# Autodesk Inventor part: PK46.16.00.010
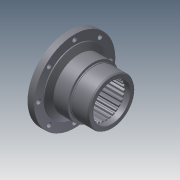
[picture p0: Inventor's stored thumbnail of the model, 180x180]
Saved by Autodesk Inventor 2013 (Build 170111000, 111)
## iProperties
Shininess: 25.0
Length Units: 11269
Angle Units: 11279
Time Units: 11290
Mass Units: 11283
Length Display Precision: 3
Angle Display Precision: 2
Created: 2001-08
Part Number: PK46.16.00.010
Material: Steel, Mild
Document SubType Name: Modeling
Designer: SOleg
Density: 7.86 g/cm^3
Mass: 4404.42 g
Surface Area: 1072.64 cm^2
Volume: 560.359 cm^3
Density: 0.0
Volumn: 0.0
Area: 0.0
PropertySet Name: Model Information
Control State: 0
Master: False
Checked Out: False
Checked Out Date: 2008-10-09
Last Check In Date: 2008-10-09
Author: SOleg
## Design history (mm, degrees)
sketch "Sketch1"
  geometry: L1 (45, 40)-(45, 48.268); L2 (33, 40)-(45, 40); L3 (33, 40.5)-(33, 40); L4 (-22, 40.5)-(33, 40.5); L5 (-22, 35)-(-22, 40.5); L6 (-26, 35)-(-22, 35); L7 (-26, 40)-(-26, 35); L8 (-33, 40)-(-26, 40); L9 (-33, 35)-(-33, 40); L10 (-40, 35)-(-33, 35); L11 (-40, 45)-(-40, 35); L12 (-45, 45)-(-40, 45); L13 (-45, 55)-(-45, 45); L14 (7, 55)-(-45, 55); L15 (7, 49)-(7, 55); L16 (12, 49)-(7, 49); L17 (12, 50)-(12, 49); L18 (42, 50)-(12, 50); L19 (45, 48.268)-(42, 50); L20 (-45, 0)-(45, 0); L21 (-45, 0)-(45, 0)
  constraints: 42 end point, 10 horizontal, 9 vertical, 2 collinear, 1 other
  dimensions: "d1" = 50 vertical distance of L18.start L20.end; "d3" = 40 distance of L1.start L20.end; "d5" = 40.5 vertical distance of L3.start L20.end; "d7" = 35 vertical distance of L5.start L20.start; "d9" = 45 vertical distance of L11.start L20.start; "d11" = 55 distance of L13.start L20.start; "d13" = 67 horizontal distance of L4.start L1.end; "d15" = 12 distance of L2.start L1.start; "d17" = 5 distance of L16.start L15.start; "d19" = 90 horizontal distance of L1.start L12.start; "d23" = 18 horizontal distance of L4.start L10.start; "d25" = 7 distance of L8.start L7.start; "d27" = 7 distance of L10.start L9.start; "d29" = 30 deg angle of L18 L19; "d31" = 3 horizontal distance of L1.end L18.start; "d33" = 49 vertical distance of L16.start L20.end; "d90" = 38 distance between parallel lines of L15 L1
revolve "RevolutionFull1" sketch "Sketch1" stored, may be unused: angle "d34" = 360 deg
workplane "Work Plane1"
node "WorkPlane1"
sketch "Sketch2"
  geometry: L1 (-41.54, -4.27)-(-37.25, -1.145); L2 (-41.54, 4.27)-(-41.54, -4.27); L3 (-37.25, 1.145)-(-41.54, 4.27); L4 (-37.25, -1.145)-(-37.25, 1.145); C1 r 55 at (0, 0) reference; C2 r 35 at (0, 0) reference
  constraints: 8 end point, 2 vertical
  dimensions: "d41" = 8.54 distance of L2.start L1.start; "d43" = 2.29 distance of L1.end L3.start; "d45" = 4.29 horizontal distance of L3.start L2.start; "d47" = 4.27 vertical distance of L1.start C1.centre; "d49" = 1.145 vertical distance of L1.end C2.centre; "d51" = 37.25 horizontal distance of L3.start C2.centre
extrude "ExtrusionBlind1" join sketch "Sketch2" distance "d52" = 55; taper "d53" = 0 deg
node "WorkPlane2"
node "WorkPlane3"
sketch "Sketch3"
  geometry: L1 (18.5, -87.5)-(18.5, -67.5); L2 (32.5, -87.5)-(18.5, -87.5); L3 (32.5, -67.5)-(32.5, -87.5); L4 (28.5, -67.5)-(32.5, -67.5); L5 (28.5, -55)-(28.5, -67.5); L6 (9.283, -55)-(28.5, -55); L7 (16.5, -67.5)-(9.283, -55); L8 (28.5, 45)-(28.5, -45) reference; L9 (23.5, 35)-(23.5, -35) reference; L10 (-184.647, 0)-(153.932, 0); L11 (-61.5, 48.268)-(-61.5, -48.268) reference; L12 (28.5, 55)-(28.5, -55) reference; L13 (28.5, -55)-(-23.5, -55) reference; L14 (28.5, 0)-(80.478, 0); L15 (28.5, -55)-(28.5, -55); L16 (16.5, -67.5)-(18.5, -67.5); L17 (16.5, -67.5)-(18.5, -67.5); L18 (9.283, -55)-(28.5, -55)
  constraints: 27 end point, 3 collinear, 3 horizontal, 3 parallel, 3 vertical, 1 midpoint, 1 perpendicular
  dimensions: "d66" = 14 distance of L2.start L1.start; "d91" = 175 diameter of L2 L10; "d92" = 135 diameter of L4 L10; "d93" = 94 distance between parallel lines of L3 L11; "d94" = 2 distance of L7.start L1.end; "d95" = 135 diameter of L16 L10; "d99" = 4 distance of L4.start L3.start; "d100" = 60 deg angle of L7 L13
revolve "RevolutionAngle1" sketch "Sketch3" stored, may be unused: angle "d69" = 360 deg
workaxis "Work Axis2"
sketch "Sketch7"
  geometry: C1 r 87.5 at (0, 0) reference; C2 r 5 at (0, 77.5)
  constraints: 1 centre point
  dimensions: "d101" = 10 diameter of C2; "d102" = 0 horizontal distance of C1.centre C2.centre; "d103" = 77.5 distance of C1.centre C2.centre
extrude "Extrusion3" cut sketch "Sketch7" stored distance "d104" = 10; taper "d105" = 0 deg
pattern_circular "Circular Pattern3" dims angle "d108" = 360 deg
sketch "Sketch8"
  geometry: L1 (-67.8, 0)-(63.8, 0) reference; L2 (7, 55)-(-45, 55) reference; L3 (7, 49)-(12, 49) reference; L4 (7, 55)-(5, 55); L5 (5, 55)-(5, 50); L6 (5, 50)-(7, 50); L7 (7, 50)-(7, 55); L8 (5, 68)-(5, -68) reference; L9 (12, 50)-(42, 50) reference; 1 further point
  constraints: 10 end point, 2 collinear, 2 parallel, 1 horizontal, 1 perpendicular, 1 vertical, 2 other
revolve "Revolution4" sketch "Sketch8" stored, may be unused: angle "d109" = 90 deg
body "Solid1"
pattern_circular "PolarArray1" dims angle "d56" = 360 deg
other parameters: "d4" = 40.5 (derived), "d6" = 35 (derived), "d8" = 45 (derived), "d10" = 55 (derived), "d12" = 67 (derived), "d14" = 12 (derived), "d16" = 5 (derived), "d20" = 28 (derived), "d22" = 18 (derived), "d24" = 7 (derived), "d26" = 7 (derived), "d28" = 30 deg (derived), "d30" = 3 (derived), "d32" = 49 (derived), "d35" = 0, "d36" = 0, "d37" = 0, "d38" = 0, "d40" = 8.54 (derived), "d42" = 2.29 (derived), "d44" = 4.29 (derived), "d46" = 4.27 (derived), "d48" = 1.145 (derived), "d50" = 37.25 (derived), "d57" = 0, "d58" = -55, "d59" = 4 (derived), "d61" = 1 (derived), "d63" = 12 (derived), "d65" = 17 (derived), "d67" = 75 deg (derived), "d71" = 0, "d72" = 0, "d77" = 14 (derived), "d79" = 102.5 (derived), "d81" = 0 (derived)
